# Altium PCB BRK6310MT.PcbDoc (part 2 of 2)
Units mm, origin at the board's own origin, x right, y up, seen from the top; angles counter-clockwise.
Board outline 165 x 90 mm, 4 copper layers (L1-Top, L2-Plane-1, L3-Plane-2, L4-Bottom), stack 1.539 mm thick; 47 components, 158 nets, 545 pads, 116 vias.
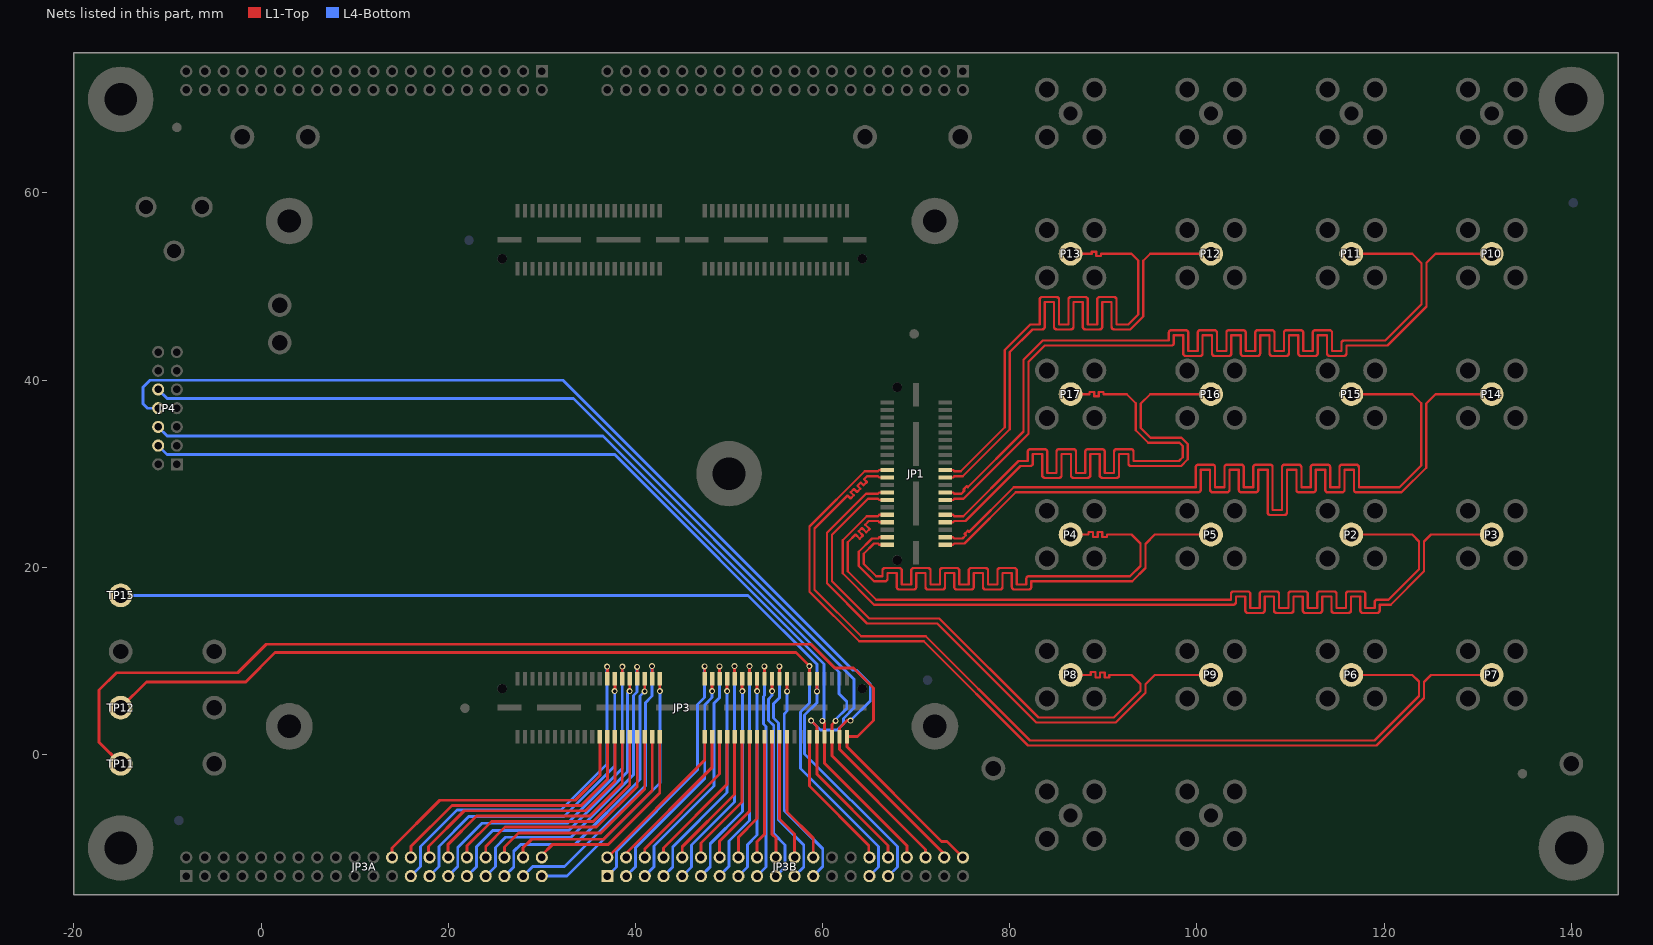
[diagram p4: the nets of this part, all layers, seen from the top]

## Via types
v1: diameter 0.635, hole 0.381, L1-Top to L4-Bottom, tented both sides, 108 vias
v2: diameter 0.889, hole 0.508, L1-Top to L4-Bottom, tented both sides, 5 vias
v3: diameter 1.27, hole 0.711, L1-Top to L4-Bottom, tented both sides, 3 vias

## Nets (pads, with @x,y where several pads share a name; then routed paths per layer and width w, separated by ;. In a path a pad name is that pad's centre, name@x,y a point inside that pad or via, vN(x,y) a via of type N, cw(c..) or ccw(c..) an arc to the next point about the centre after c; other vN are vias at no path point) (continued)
JP3_24: JP3.24 JP3A.24 | length 30.6
  L1-Top w0.305: JP3A.24@14,-11 14,-9.981 19.091,-4.891 33.569,-4.891 36.199,-2.261 JP3.24@36.199,1.914
JP3_25: JP3.25 JP3A.25 | length 38.9
  L1-Top w0.305: v1(36.972,9.384) 36.999,9.357 JP3.25@36.999,8.086
  L4-Bottom w0.305: JP3A.25@16,-13 17.033,-11.967 17.033,-9.844 20.945,-5.932 32.045,-5.932 36.972,-1.005 v1(36.972,9.384)
JP3_26: JP3.26 JP3A.26 | length 29.7
  L1-Top w0.305: JP3A.26@16,-11 16,-9.836 20.386,-5.45 34.204,-5.45 36.999,-2.654 JP3.26@36.999,1.914
JP3_27: JP3.27 JP3A.27 | length 35.3
  L1-Top w0.305: v1(37.785,6.768) 37.799,6.782 JP3.27@37.799,8.086
  L4-Bottom w0.305: JP3A.27@18,-13 19.014,-11.986 19.014,-9.818 22.189,-6.643 32.375,-6.643 37.785,-1.233 v1(37.785,6.768)
JP3_28: JP3.28 JP3A.28 | length 28.8
  L1-Top w0.305: JP3A.28@18,-11 17.897,-10.897 17.897,-9.818 21.707,-6.008 34.661,-6.008 37.799,-2.87 JP3.28@37.799,1.914
JP3_29: JP3.29 JP3A.29 | length 36.7
  L1-Top w0.305: v1(38.598,9.384) 38.599,9.383 JP3.29@38.599,8.086
  L4-Bottom w0.305: JP3A.29@20,-13 21.021,-11.979 21.021,-9.945 23.612,-7.355 32.73,-7.355 38.598,-1.487 v1(38.598,9.384)
JP3_30: JP3.30 JP3A.30 | length 27.8
  L1-Top w0.305: JP3A.30@20,-11 19.954,-10.954 19.954,-9.641 23.002,-6.593 35.118,-6.593 38.599,-3.111 JP3.30@38.599,1.914
JP3_31: JP3.31 JP3A.31 | length 33.1
  L1-Top w0.305: v1(39.385,6.768) 39.399,6.782 JP3.31@39.399,8.086
  L4-Bottom w0.305: JP3A.31@22,-13 23.002,-11.998 23.002,-9.869 24.755,-8.117 32.883,-8.117 39.157,-1.843 39.157,6.539 v1(39.385,6.768)
JP3_32: JP3.32 JP3A.32 | length 26.5
  L1-Top w0.305: JP3A.32@22,-11 22,-9.754 24.602,-7.151 35.499,-7.151 39.399,-3.251 JP3.32@39.399,1.914
JP3_33: JP3.33 JP3A.33 | length 34.4
  L1-Top w0.305: v1(40.173,9.359) 40.199,9.332 JP3.33@40.199,8.086
  L4-Bottom w0.305: JP3A.33@24,-13 25.034,-11.966 25.034,-9.945 26.126,-8.853 33.111,-8.853 39.792,-2.173 39.792,6.285 40.173,6.666 v1(40.173,9.359)
JP3_34: JP3.34 JP3A.34 | length 25.4
  L1-Top w0.305: JP3A.34@24,-11 24,-9.837 26.076,-7.761 35.855,-7.761 40.199,-3.416 JP3.34@40.199,1.914
JP3_35: JP3.35 JP3A.35 | length 30.7
  L1-Top w0.305: v1(40.985,6.742) 40.999,6.756 JP3.35@40.999,8.086
  L4-Bottom w0.305: JP3A.35@26,-13 26.99,-12.01 26.99,-10.352 27.701,-9.641 33.518,-9.641 40.477,-2.681 40.477,6.234 v1(40.985,6.742)
JP3_36: JP3.36 JP3A.36 | length 24.3
  L1-Top w0.305: JP3A.36@26,-11 26,-9.894 27.498,-8.396 36.286,-8.396 40.999,-3.683 JP3.36@40.999,1.914
JP3_37: JP3.37 JP3A.37 | length 31.5
  L1-Top w0.305: JP3.37@41.8,8.086 v1@41.8,9.408
  L4-Bottom w0.305: JP3A.37@28,-13 29.023,-11.977 32.426,-11.977 41.062,-3.341 41.062,5.523 41.773,6.234 v1(41.773,9.435)
JP3_38: JP3.38 JP3A.38 | length 23.1
  L1-Top w0.305: JP3A.38@28,-11 28,-9.977 28.92,-9.056 36.591,-9.056 41.8,-3.848 JP3.38@41.8,1.914
JP3_39: JP3.39 JP3A.39 | length 27.9
  L1-Top w0.305: JP3.39@42.6,8.086 42.6,6.779 v1(42.611,6.768)
  L4-Bottom w0.305: JP3A.39@30,-13 32.673,-13 42.611,-3.062 v1(42.611,6.768)
JP3_40: JP3.40 JP3A.40 | length 21.6
  L1-Top w0.305: JP3A.40@30,-11 30,-10.745 31.105,-9.641 37.074,-9.641 42.6,-4.115 JP3.40@42.6,1.914
JP3_41: JP3.41 JP3B.1 | length 28
  L1-Top w0.305: v1(47.386,9.409) 47.4,9.395 JP3.41@47.4,8.086
  L4-Bottom w0.305: JP3B.1@37,-13 37.963,-12.037 37.963,-10.352 46.65,-1.665 46.65,5.345 47.386,6.082 v1(47.386,9.409)
JP3_42: JP3.42 JP3B.2 | length 17.2
  L1-Top w0.305: JP3B.2@37,-11 47.4,-0.6 JP3.42@47.4,1.914
JP3_43: JP3.43 JP3B.3 | length 24.9
  L1-Top w0.305: v1(48.199,6.768) v1(48.199,6.768) JP3.43@48.2,8.086
  L4-Bottom w0.305: JP3B.3@39,-13 39.995,-12.005 39.995,-9.971 47.412,-2.554 47.412,5.295 48.199,6.082 v1(48.199,6.768)
JP3_44: JP3.44 JP3B.4 | length 16.7
  L1-Top w0.305: JP3B.4@39,-11 39,-10.575 48.2,-1.374 JP3.44@48.2,1.914
JP3_45: JP3.45 JP3B.5 | length 27
  L1-Top w0.305: v1(48.986,9.409) 49,9.395 JP3.45@49,8.086
  L4-Bottom w0.305: JP3B.5@41,-13 42.001,-11.999 42.001,-9.768 48.402,-3.367 48.402,5.472 48.986,6.057 v1(48.986,9.409)
JP3_46: JP3.46 JP3B.6 | length 16.2
  L1-Top w0.305: JP3B.6@41,-11 41,-10.099 49,-2.098 JP3.46@49,1.914
JP3_47: JP3.47 JP3B.7 | length 23.9
  L1-Top w0.305: v1(49.799,6.768) v1(49.799,6.768) JP3.47@49.801,8.086
  L4-Bottom w0.305: JP3B.7@43,-13 43.983,-12.017 43.983,-9.895 49.799,-4.078 v1(49.799,6.768)
JP3_48: JP3.48 JP3B.8 | length 15.7
  L1-Top w0.305: JP3B.8@43,-11 43,-9.988 49.801,-3.188 JP3.48@49.801,1.914
JP3_49: JP3.49 JP3B.9 | length 26.1
  L1-Top w0.305: v1(50.587,9.435) 50.601,9.421 JP3.49@50.601,8.086
  L4-Bottom w0.305: JP3B.9@45,-13 45.989,-12.011 45.989,-9.691 50.587,-5.094 v1(50.587,9.435)
JP3_50: JP3.50 JP3B.10 | length 15.2
  L1-Top w0.305: JP3B.10@45,-11 45,-9.868 50.601,-4.267 JP3.50@50.601,1.914
JP3_51: JP3.51 JP3B.11 | length 22.9
  L1-Top w0.305: JP3.51@51.401,8.086 51.401,6.792 v1(51.425,6.768)
  L4-Bottom w0.305: JP3B.11@47,-13 47.996,-12.004 47.996,-9.539 51.425,-6.11 v1(51.425,6.768)
JP3_52: JP3.52 JP3B.12 | length 14.7
  L1-Top w0.305: JP3B.12@47,-11 47,-9.468 51.401,-5.067 JP3.52@51.401,1.914
JP3_53: JP3.53 JP3B.13 | length 25.1
  L1-Top w0.305: v1(52.187,9.435) 52.201,9.421 JP3.53@52.201,8.086
  L4-Bottom w0.305: JP3B.13@49,-13 49,-12.954 50.002,-11.952 50.002,-9.234 52.187,-7.05 v1(52.187,9.435)
JP3_54: JP3.54 JP3B.14 | length 14.2
  L1-Top w0.305: JP3B.14@49,-11 49,-9.271 52.201,-6.071 JP3.54@52.201,1.914
JP3_55: JP3.55 JP3B.15 | length 21.9
  L1-Top w0.305: v1(53,6.768) v1(53,6.768) JP3.55@53.001,8.086
  L4-Bottom w0.305: JP3B.15@51,-13 51.984,-12.016 51.984,-9.641 53,-8.625 v1(53,6.768)
JP3_56: JP3.56 JP3B.16 | length 13.7
  L1-Top w0.305: JP3B.16@51,-11 51,-8.846 53.001,-6.845 JP3.56@53.001,1.914
JP3_57: JP3.57 JP3B.17 | length 24.3
  L1-Top w0.305: v1(53.787,9.409) 53.801,9.395 JP3.57@53.801,8.086
  L4-Bottom w0.305: JP3B.17@53,-13 53.965,-12.035 53.965,2.983 53.685,3.263 53.685,6.184 53.787,6.285 v1(53.787,9.409)
JP3_58: JP3.58 JP3B.18 | length 13.2
  L1-Top w0.305: JP3B.18@53,-11 53,-9.335 53.801,-8.534 JP3.58@53.801,1.914
JP3_59: JP3.59 JP3B.19 | length 22.4
  L1-Top w0.305: v1(54.6,6.768) v1(54.6,6.768) JP3.59@54.601,8.086
  L4-Bottom w0.305: v1(54.6,6.768) 54.6,6.285 54.219,5.904 54.219,3.644 54.778,3.085 54.778,-8.472 55.971,-9.666 55.971,-12.054 55.025,-13 JP3B.19@55,-13
JP3_60: JP3.60 JP3B.20 | length 13.1
  L1-Top w0.305: JP3.60@54.601,1.914 54.601,-8.524 55.006,-8.929 55.006,-10.994 JP3B.20@55,-11
JP3_61: JP3.61 JP3B.21 | length 25.7
  L1-Top w0.305: v1(55.387,9.409) 55.401,9.395 JP3.61@55.401,8.086
  L4-Bottom w0.305: v1(55.387,9.409) 55.387,6.057 54.752,5.422 54.752,3.898 55.286,3.364 55.286,-6.999 57.978,-9.691 57.978,-12.022 JP3B.21@57,-13
JP3_62: JP3.62 JP3B.22 | length 13.6
  L1-Top w0.305: JP3.62@55.401,1.914 55.401,-6.886 57,-8.485 JP3B.22@57,-11
JP3_63: JP3.63 JP3B.23 | length 23.3
  L1-Top w0.305: v1(56.2,6.742) v1(56.2,6.742) JP3.63@56.201,8.086
  L4-Bottom w0.305: v1(56.2,6.742) 56.2,4.634 55.895,4.329 55.895,-5.958 60.01,-10.072 60.01,-11.99 JP3B.23@59,-13
JP3_64: JP3.64 JP3B.24 | length 14.1
  L1-Top w0.305: JP3.64@56.201,1.914 56.201,-6.162 59,-8.961 JP3B.24@59,-11
JP3_69: JP3.69 JP3B.29 TP12.1 | length 104.7
  L1-Top w0.305: TP12.1@-15,5 -12.242,7.758 -1.636,7.758 1.488,10.883 57.14,10.883 v1(58.588,9.435) 58.602,9.421 JP3.69@58.602,8.086
  L4-Bottom w0.305: v1(58.588,9.435) 58.588,5.498 57.622,4.533 57.622,-1.487 65.979,-9.844 65.979,-12.021 JP3B.29@65,-13
JP3_70: JP3.70 JP3B.30 | length 15.6
  L1-Top w0.305: JP3.70@58.602,1.914 58.602,-3.381 64.938,-9.717 64.938,-10.938 JP3B.30@65,-11
JP3_80: JP3.80 JP3B.40 TP11.1 | length 120.9
  L1-Top w0.305: TP11.1@-15,-1 -17.308,1.308 -17.308,6.869 -15.453,8.724 -2.499,8.724 0.549,11.772 58.765,11.772 61.305,9.232 63.312,9.232 65.446,7.098 65.446,3.644 63.716,1.914 JP3.80@62.602,1.914 62.602,0.823 72.71,-9.285 73.285,-9.285 JP3B.40@75,-11
JTAG_TCK: JP3.76 JP3B.36 JP4.6 | length 108.5
  L1-Top w0.305: v1(61.382,3.593) 61.002,3.213 JP3.76@61.002,1.914 61.002,-0.142 71,-10.14 JP3B.36@71,-11
  L4-Bottom w0.305: JP4.6@-11,35 -10.022,34.022 36.54,34.022 61.763,8.8 61.763,6.488 62.575,5.676 62.575,4.914 61.382,3.72 v1(61.382,3.593)
JTAG_TDI: JP3.72 JP3B.32 JP4.10 | length 114.6
  L1-Top w0.305: v1(58.765,3.618) 59.402,2.982 JP3.72@59.402,1.914 59.402,-2.124 67,-9.722 JP3B.32@67,-11
  L4-Bottom w0.305: JP4.10@-11,39 -10.035,38.035 33.365,38.035 63.363,8.038 63.363,4.99 62.22,3.847 62.22,3.288 61.534,2.602 59.781,2.602 v1(58.765,3.618)
JTAG_TDO: JP3.78 JP3B.38 JP4.8 | length 119.8
  L1-Top w0.305: v1(62.982,3.618) 62.601,3.618 61.802,2.819 JP3.78@61.802,1.914 61.802,0.556 73,-10.642 JP3B.38@73,-11
  L4-Bottom w0.305: JP4.8@-11,37 -12.145,37 -12.151,36.994 -12.634,37.476 -12.634,39.229 -11.872,39.991 32.273,39.991 63.264,9 63.594,9 65.09,7.504 65.09,5.726 v1(62.982,3.618)
JTAG_TMS: JP3.74 JP3B.34 JP4.4 | length 105.3
  L1-Top w0.305: v1(59.985,3.593) 60.202,3.375 JP3.74@60.202,1.914 60.202,-0.943 69,-9.741 JP3B.34@69,-11
  L4-Bottom w0.305: JP4.4@-11,33 -10.041,32.041 37.785,32.041 60.162,9.663 60.162,3.771 v1(59.985,3.593)
RX101_0N: JP1.3 P5.1 | length 63.5
  L1-Top w0.241: JP1.3@66.914,23.199 66.058,23.199 65.925,23.066 65.273,23.066 63.869,21.661 63.869,20.131 65.5,18.5 66.658,18.5 ccw(c66.658,18.767) 66.925,18.767 66.925,19.384 67.928,19.384 67.928,17.883 ccw(c68.195,17.883) 68.195,17.616 69.732,17.616 ccw(c69.732,17.883) 69.999,17.883 69.999,19.384 71.002,19.384 71.002,17.883 ccw(c71.269,17.883) 71.269,17.616 72.805,17.616 ccw(c72.805,17.883) 73.072,17.883 73.072,19.384 74.075,19.384 74.075,17.883 ccw(c74.342,17.883) 74.342,17.616 75.879,17.616 ccw(c75.879,17.883) 76.145,17.883 76.145,19.384 77.149,19.384 77.149,17.883 ccw(c77.415,17.883) 77.415,17.616 78.952,17.616 ccw(c78.952,17.883) 79.219,17.883 79.219,19.384 80.222,19.384 80.222,17.883 ccw(c80.489,17.883) 80.489,17.616 82.025,17.616 ccw(c82.025,17.883) 82.292,17.883 82.292,18.5 93.078,18.5 94.5,19.922 94.5,22.5 95.5,23.5 P5.1@101.5,23.5
RX101_0P: JP1.1 P4.1 | length 63.5
  L1-Top w0.241: JP1.1@66.914,22.399 66.058,22.399 65.925,22.532 65.494,22.532 64.402,21.44 64.402,20.352 65.721,19.033 66.392,19.033 66.392,19.651 cw(c66.658,19.651) 66.658,19.917 68.195,19.917 cw(c68.195,19.651) 68.462,19.651 68.462,18.149 69.465,18.149 69.465,19.651 cw(c69.732,19.651) 69.732,19.917 71.269,19.917 cw(c71.269,19.651) 71.535,19.651 71.535,18.149 72.539,18.149 72.539,19.651 cw(c72.805,19.651) 72.805,19.917 74.342,19.917 cw(c74.342,19.651) 74.609,19.651 74.609,18.149 75.612,18.149 75.612,19.651 cw(c75.879,19.651) 75.879,19.917 77.415,19.917 cw(c77.415,19.651) 77.682,19.651 77.682,18.149 78.685,18.149 78.685,19.651 cw(c78.952,19.651) 78.952,19.917 80.489,19.917 cw(c80.489,19.651) 80.755,19.651 80.755,18.149 81.759,18.149 81.759,18.767 cw(c82.025,18.767) 82.025,19.033 92.857,19.033 93.967,20.143 93.967,22.533 93,23.5 90.382,23.5 90.382,23.233 89.887,23.233 89.887,23.767 89.391,23.767 89.391,23.233 88.896,23.233 88.896,23.767 88.401,23.767 88.401,23.5 P4.1@86.5,23.5
RX101_1N: JP1.15 P9.1 | length 63.5
  L1-Top w0.241: JP1.15@66.914,28 66.058,28 65.925,27.866 64.638,27.866 60.467,23.695 60.467,18.288 64.754,14 72.246,14 82.84,3.406 91.319,3.406 94.5,6.587 94.5,7.5 95.5,8.5 P9.1@101.5,8.5
RX101_1P: JP1.13 P8.1 | length 63.5
  L1-Top w0.241: JP1.13@66.914,27.2 66.058,27.2 65.925,27.333 64.859,27.333 61,23.474 61,18.509 64.975,14.533 72.467,14.533 83.061,3.939 91.098,3.939 93.967,6.808 93.967,7.533 93,8.5 90.636,8.5 90.636,8.233 90.141,8.233 90.141,8.767 89.645,8.767 89.645,8.233 89.15,8.233 89.15,8.8 88.655,8.8 88.655,8.5 P8.1@86.5,8.5
RX123_0N: JP1.22 P13.1 | length 63.5
  L1-Top w0.241: JP1.22@73.086,30.4 73.932,30.4 74.066,30.267 74.767,30.267 79.467,34.967 79.467,43.221 82.197,45.951 83.196,45.951 83.196,48.61 cw(c83.463,48.61) 83.463,48.876 85,48.876 cw(c85,48.61) 85.266,48.61 85.266,45.951 86.27,45.951 86.27,48.61 cw(c86.536,48.61) 86.536,48.876 88.073,48.876 cw(c88.073,48.61) 88.34,48.61 88.34,45.951 89.343,45.951 89.343,48.61 cw(c89.61,48.61) 89.61,48.876 91.146,48.876 cw(c91.146,48.61) 91.413,48.61 91.413,45.951 92.648,45.951 93.717,47.02 93.717,52.783 93,53.5 89.747,53.5 89.747,53.271 89.252,53.271 89.252,53.729 88.756,53.729 88.756,53.5 P13.1@86.5,53.5
RX123_0P: JP1.20 P12.1 | length 63.5
  L1-Top w0.241: JP1.20@73.086,29.6 73.932,29.6 74.066,29.733 74.988,29.733 80,34.746 80,43 82.418,45.418 83.463,45.418 ccw(c83.463,45.684) 83.73,45.684 83.73,48.343 84.733,48.343 84.733,45.684 ccw(c85,45.684) 85,45.418 86.536,45.418 ccw(c86.536,45.684) 86.803,45.684 86.803,48.343 87.806,48.343 87.806,45.684 ccw(c88.073,45.684) 88.073,45.418 89.61,45.418 ccw(c89.61,45.684) 89.876,45.684 89.876,48.343 90.88,48.343 90.88,45.684 ccw(c91.146,45.684) 91.146,45.418 92.869,45.418 94.25,46.799 94.25,52.75 95,53.5 P12.1@101.5,53.5
RX123_1N: JP1.10 P17.1 | length 63.5
  L1-Top w0.241: JP1.10@73.086,25.599 73.932,25.599 74.066,25.466 75.04,25.466 80.929,31.355 81.928,31.355 81.928,32.358 cw(c82.195,32.358) 82.195,32.625 83.732,32.625 cw(c83.732,32.358) 83.998,32.358 83.998,30.085 85.002,30.085 85.002,32.358 cw(c85.268,32.358) 85.268,32.625 86.805,32.625 cw(c86.805,32.358) 87.072,32.358 87.072,30.085 88.075,30.085 88.075,32.358 cw(c88.342,32.358) 88.342,32.625 89.878,32.625 cw(c89.878,32.358) 90.145,32.358 90.145,30.085 91.148,30.085 91.148,32.358 cw(c91.415,32.358) 91.415,32.625 92.952,32.625 cw(c92.952,32.358) 93.218,32.358 93.218,31.355 98.092,31.355 98.491,31.754 98.491,32.955 98.135,33.311 94.808,33.311 93.467,34.652 93.467,37.533 92.5,38.5 90.014,38.5 90.014,38.729 89.518,38.729 89.518,38.271 89.023,38.271 89.023,38.729 88.528,38.729 88.528,38.5 P17.1@86.5,38.5
RX123_1P: JP1.8 P16.1 | length 63.5
  L1-Top w0.241: JP1.8@73.086,24.799 73.932,24.799 74.066,24.933 75.261,24.933 81.15,30.822 82.195,30.822 ccw(c82.195,31.088) 82.462,31.088 82.462,32.092 83.465,32.092 83.465,29.818 ccw(c83.732,29.818) 83.732,29.552 85.268,29.552 ccw(c85.268,29.818) 85.535,29.818 85.535,32.092 86.538,32.092 86.538,29.818 ccw(c86.805,29.818) 86.805,29.552 88.342,29.552 ccw(c88.342,29.818) 88.608,29.818 88.608,32.092 89.612,32.092 89.612,29.818 ccw(c89.878,29.818) 89.878,29.552 91.415,29.552 ccw(c91.415,29.818) 91.682,29.818 91.682,32.092 92.685,32.092 92.685,31.088 ccw(c92.952,31.088) 92.952,30.822 98.313,30.822 99.024,31.533 99.024,33.176 98.356,33.844 95.029,33.844 94,34.873 94,37.5 95,38.5 P16.1@101.5,38.5
TX101_0N: JP1.9 P3.1 | length 101.6
  L1-Top w0.241: JP1.9@66.914,25.599 66.058,25.599 65.925,25.466 64.714,25.466 62.141,22.893 62.141,19.359 65.5,16 99.507,16 103.895,16 ccw(c103.895,16.267) 104.162,16.267 104.162,16.884 105.165,16.884 105.165,15.383 ccw(c105.432,15.383) 105.432,15.116 106.968,15.116 ccw(c106.968,15.383) 107.235,15.383 107.235,16.884 108.238,16.884 108.238,15.383 ccw(c108.505,15.383) 108.505,15.116 110.042,15.116 ccw(c110.042,15.383) 110.308,15.383 110.308,16.884 111.312,16.884 111.312,15.383 ccw(c111.578,15.383) 111.578,15.116 113.115,15.116 ccw(c113.115,15.383) 113.382,15.383 113.382,16.884 114.385,16.884 114.385,15.383 ccw(c114.652,15.383) 114.652,15.116 116.188,15.116 ccw(c116.188,15.383) 116.455,15.383 116.455,16.884 117.458,16.884 117.458,15.383 ccw(c117.725,15.383) 117.725,15.116 119.262,15.116 ccw(c119.262,15.383) 119.529,15.383 119.529,16 120.702,16 124.267,19.565 124.267,22.767 125,23.5 P3.1@131.5,23.5
TX101_0P: JP1.7 P2.1 | length 101.6
  L1-Top w0.241: JP1.7@66.914,24.799 66.058,24.799 65.925,24.933 64.935,24.933 64.559,24.557 65.027,24.089 64.677,23.738 64.209,24.206 63.859,23.856 64.327,23.388 63.976,23.038 63.509,23.506 62.675,22.672 62.675,19.58 65.721,16.533 99.507,16.533 103.628,16.533 103.628,17.151 cw(c103.895,17.151) 103.895,17.417 105.432,17.417 cw(c105.432,17.151) 105.698,17.151 105.698,15.649 106.702,15.649 106.702,17.151 cw(c106.968,17.151) 106.968,17.417 108.505,17.417 cw(c108.505,17.151) 108.772,17.151 108.772,15.649 109.775,15.649 109.775,17.151 cw(c110.042,17.151) 110.042,17.417 111.578,17.417 cw(c111.578,17.151) 111.845,17.151 111.845,15.649 112.848,15.649 112.848,17.151 cw(c113.115,17.151) 113.115,17.417 114.652,17.417 cw(c114.652,17.151) 114.918,17.151 114.918,15.649 115.922,15.649 115.922,17.151 cw(c116.188,17.151) 116.188,17.417 117.725,17.417 cw(c117.725,17.151) 117.992,17.151 117.992,15.649 118.995,15.649 118.995,16.267 cw(c119.262,16.267) 119.262,16.533 120.481,16.533 123.733,19.786 123.733,22.767 123,23.5 P2.1@116.5,23.5
TX101_1N: JP1.21 P7.1 | length 101.6
  L1-Top w0.241: JP1.21@66.914,30.4 66.058,30.4 65.925,30.267 64.512,30.267 58.611,24.365 58.611,17.389 63.907,12.093 70.81,12.093 81.937,0.967 119.182,0.967 124.25,6.035 124.25,7.75 125,8.5 P7.1@131.5,8.5
TX101_1P: JP1.19 P6.1 | length 101.6
  L1-Top w0.241: JP1.19@66.914,29.6 66.058,29.6 65.925,29.733 64.733,29.733 64.417,29.417 64.731,29.103 64.381,28.753 64.067,29.067 63.717,28.717 64.031,28.402 63.681,28.052 63.366,28.366 63.016,28.016 63.33,27.702 62.98,27.352 62.666,27.666 59.144,24.144 59.144,17.61 64.128,12.626 71.031,12.626 82.158,1.5 118.961,1.5 123.717,6.256 123.717,7.783 123,8.5 P6.1@116.5,8.5
TX123_0N: JP1.16 P11.1 | length 101.6
  L1-Top w0.241: JP1.16@73.086,28 73.932,28 74.066,27.866 74.841,27.866 75.171,28.196 75.045,28.322 75.396,28.672 75.521,28.546 81.471,34.496 81.471,42.184 83.51,44.224 96.999,44.224 96.999,45.062 cw(c97.265,45.062) 97.265,45.329 98.802,45.329 cw(c98.802,45.062) 99.069,45.062 99.069,43.119 100.072,43.119 100.072,45.062 cw(c100.339,45.062) 100.339,45.329 101.876,45.329 cw(c101.876,45.062) 102.142,45.062 102.142,43.119 103.146,43.119 103.146,45.062 cw(c103.412,45.062) 103.412,45.329 104.949,45.329 cw(c104.949,45.062) 105.216,45.062 105.216,43.119 106.219,43.119 106.219,45.062 cw(c106.486,45.062) 106.486,45.329 108.022,45.329 cw(c108.022,45.062) 108.289,45.062 108.289,43.119 109.292,43.119 109.292,45.062 cw(c109.559,45.062) 109.559,45.329 111.096,45.329 cw(c111.096,45.062) 111.362,45.062 111.362,43.119 112.366,43.119 112.366,45.062 cw(c112.632,45.062) 112.632,45.329 114.169,45.329 cw(c114.169,45.062) 114.436,45.062 114.436,43.119 115.439,43.119 115.439,43.957 cw(c115.706,43.957) 115.706,44.224 120.13,44.224 124,48.093 124,52.5 123,53.5 P11.1@116.5,53.5
TX123_0P: JP1.14 P10.1 | length 101.6
  L1-Top w0.241: JP1.14@73.086,27.2 73.932,27.2 74.066,27.333 75.062,27.333 82.004,34.275 82.004,41.963 83.731,43.69 97.265,43.69 ccw(c97.265,43.957) 97.532,43.957 97.532,44.795 98.535,44.795 98.535,42.852 ccw(c98.802,42.852) 98.802,42.586 100.339,42.586 ccw(c100.339,42.852) 100.606,42.852 100.606,44.795 101.609,44.795 101.609,42.852 ccw(c101.876,42.852) 101.876,42.586 103.412,42.586 ccw(c103.412,42.852) 103.679,42.852 103.679,44.795 104.682,44.795 104.682,42.852 ccw(c104.949,42.852) 104.949,42.586 106.486,42.586 ccw(c106.486,42.852) 106.752,42.852 106.752,44.795 107.756,44.795 107.756,42.852 ccw(c108.022,42.852) 108.022,42.586 109.559,42.586 ccw(c109.559,42.852) 109.826,42.852 109.826,44.795 110.829,44.795 110.829,42.852 ccw(c111.096,42.852) 111.096,42.586 112.632,42.586 ccw(c112.632,42.852) 112.899,42.852 112.899,44.795 113.902,44.795 113.902,42.852 ccw(c114.169,42.852) 114.169,42.586 115.706,42.586 ccw(c115.706,42.852) 115.973,42.852 115.973,43.69 120.351,43.69 124.533,47.872 124.533,52.533 125.5,53.5 P10.1@131.5,53.5
TX123_1N: JP1.4 P15.1 | length 101.6
  L1-Top w0.241: JP1.4@73.086,23.199 73.932,23.199 74.066,23.066 74.951,23.066 75.298,23.413 75.154,23.557 75.505,23.907 75.648,23.763 80.43,28.545 99.869,28.545 99.869,30.697 cw(c100.136,30.697) 100.136,30.963 101.672,30.963 cw(c101.672,30.697) 101.939,30.697 101.939,28.545 102.942,28.545 102.942,30.697 cw(c103.209,30.697) 103.209,30.963 104.746,30.963 cw(c104.746,30.697) 105.012,30.697 105.012,28.545 106.016,28.545 106.016,30.697 cw(c106.282,30.697) 106.282,30.963 107.819,30.963 cw(c107.819,30.697) 108.086,30.697 108.086,26.126 109.089,26.126 109.089,30.697 cw(c109.356,30.697) 109.356,30.963 110.893,30.963 cw(c110.893,30.697) 111.159,30.697 111.159,28.545 112.163,28.545 112.163,30.697 cw(c112.429,30.697) 112.429,30.963 113.966,30.963 cw(c113.966,30.697) 114.233,30.697 114.233,28.545 115.236,28.545 115.236,30.697 cw(c115.503,30.697) 115.503,30.963 117.039,30.963 cw(c117.039,30.697) 117.306,30.697 117.306,28.545 121.647,28.545 123.967,30.864 123.967,37.533 123,38.5 P15.1@116.5,38.5
TX123_1P: JP1.2 P14.1 | length 101.6
  L1-Top w0.241: JP1.2@73.086,22.399 73.932,22.399 74.066,22.532 75.172,22.532 80.651,28.011 100.136,28.011 ccw(c100.136,28.278) 100.402,28.278 100.402,30.43 101.406,30.43 101.406,28.278 ccw(c101.672,28.278) 101.672,28.011 103.209,28.011 ccw(c103.209,28.278) 103.476,28.278 103.476,30.43 104.479,30.43 104.479,28.278 ccw(c104.746,28.278) 104.746,28.011 106.282,28.011 ccw(c106.282,28.278) 106.549,28.278 106.549,30.43 107.552,30.43 107.552,25.86 ccw(c107.819,25.86) 107.819,25.593 109.356,25.593 ccw(c109.356,25.86) 109.623,25.86 109.623,30.43 110.626,30.43 110.626,28.278 ccw(c110.893,28.278) 110.893,28.011 112.429,28.011 ccw(c112.429,28.278) 112.696,28.278 112.696,30.43 113.699,30.43 113.699,28.278 ccw(c113.966,28.278) 113.966,28.011 115.503,28.011 ccw(c115.503,28.278) 115.769,28.278 115.769,30.43 116.773,30.43 116.773,28.278 ccw(c117.039,28.278) 117.039,28.011 121.868,28.011 124.5,30.643 124.5,37.5 125.5,38.5 P14.1@131.5,38.5
VREF_BANK1: JP3.71 JP3B.31 TP15.1 | length 106.5
  L1-Top w0.305: v1(59.4,6.742) v1(59.4,6.742) JP3.71@59.402,8.086
  L4-Bottom w0.305: TP15.1@-15,17 52.038,17 59.4,9.638 v1(59.4,6.742) 59.4,5.523 58.08,4.202 58.08,0.062 67.986,-9.844 67.986,-12.014 JP3B.31@67,-13
pads on no net: JP1.25 JP1.27 JP1.31 JP1.33 JP1.MH JP2.MH JP3.MH JP4.12 JP4.14 P1.3

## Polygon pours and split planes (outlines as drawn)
DGND on L2-Plane-1 (split plane): 144.49,-14.49 -19.49,-14.49 -19.49,74.49 144.49,74.49
+VDC on L3-Plane-2 (split plane): 78.744,60.891 54.973,37.12 54.949,37.123 11.069,37.123 1.67,46.522 -8.236,56.428 -9.812,58.004 -9.812,60.84 -2.876,67.776 -0.142,67.776 18.63,49.005 18.683,48.964 18.745,48.938 18.811,48.93 57.953,48.93 58.019,48.938 58.081,48.964 58.134,49.005 60.166,51.037 60.206,51.09 60.219,51.121 60.232,51.151 60.241,51.218 60.241,59.062 69.234,68.055 69.274,68.108 69.3,68.169 69.309,68.236 69.309,74.49 78.744,74.49
DGND on L3-Plane-2 (split plane): 144.49,-14.49 80.256,-14.49 80.256,-13 80.247,-12.934 80.222,-12.872 80.181,-12.819 67.48,-0.117 67.48,4.507 67.48,6.692 67.471,6.758 67.445,6.82 67.405,6.873 64.687,9.591 64.634,9.631 64.572,9.657 64.506,9.666 63.037,9.666 55.256,17.447 55.256,36.678 79.181,60.603 79.222,60.656 79.24,60.7 79.247,60.718 79.256,60.784 79.256,74.49 144.49,74.49
+3.3VDD on L3-Plane-2 (split plane): 68.796,68.342 59.803,59.349 59.763,59.296 59.737,59.234 59.728,59.168 59.728,51.324 57.846,49.442 18.917,49.442 0.146,68.214 0.092,68.254 0.031,68.28 -0.036,68.289 -2.982,68.289 -3.048,68.28 -3.092,68.262 -3.11,68.254 -3.163,68.214 -10.25,61.127 -10.29,61.074 -10.316,61.012 -10.325,60.946 -10.325,57.898 -10.316,57.832 -10.29,57.77 -10.25,57.717 -8.599,56.066 -8.523,55.99 1.307,46.16 10.781,36.686 10.835,36.645 10.896,36.619 10.963,36.611 54.744,36.611 54.744,17.34 54.753,17.274 54.778,17.212 54.819,17.159 62.75,9.228 62.803,9.188 62.847,9.169 62.865,9.162 62.931,9.153 64.4,9.153 66.967,6.585 66.967,4.507 66.967,-0.224 66.976,-0.29 67.002,-0.352 67.042,-0.405 79.744,-13.106 79.744,-14.49 -19.49,-14.49 -19.49,74.49 68.796,74.49

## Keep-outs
Keep-Out Layer:
  the board outline again, w0.178

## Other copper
L3-Plane-2 (plane layer: these items are gaps in the copper):
  lines w0.508: -8.418,56.247 1.488,46.341 10.963,36.867 54.949,36.867 55,36.816 55,17.34 62.931,9.409 64.506,9.409 67.224,6.692 67.224,4.507 67.224,-0.224 80,-13 80,-15 ; -8.341,56.171 -10.069,57.898 -10.069,60.946 -2.982,68.033 -0.036,68.033 18.811,49.186 57.953,49.186 59.985,51.218 59.985,59.168 69.052,68.236 69.052,75.068 ; 55.003,36.788 79,60.784 79,75 ; 76.469,74.967 76.495,74.941

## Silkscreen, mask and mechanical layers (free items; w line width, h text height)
Top Overlay:
  lines w0.203: 0,15 0,0 15,0 ; 0,45 0,60 15,60 ; 60,0 75,0 75,15 ; 60,60 75,60 75,45
  lines w0.508: 87.5,-12.5 81,-12.5 81,-1 107,-1 107,-12 ; 87.5,2.5 81,2.5 81,14 107,14 107,3 ; 87.5,17.5 81,17.5 81,29 107,29 107,18 ; 87.5,32.5 81,32.5 81,44 107,44 107,33 ; 87.5,47.5 81,47.5 81,59 107,59 107,48 ; 87.5,62.5 81,62.5 81,74 107,74 107,63 107,62.5 101.5,62.5 ; 101.5,-12.5 107,-12.5 ; 101.5,2.5 107,2.5 ; 101.5,17.5 107,17.5 ; 101.5,32.5 107,32.5 ; 101.5,47.5 107,47.5 ; 117.5,2.5 111,2.5 111,14 137,14 137,3 ; 117.5,17.5 111,17.5 111,29 137,29 137,18 ; 117.5,32.5 111,32.5 111,44 137,44 137,33 ; 117.5,47.5 111,47.5 111,59 137,59 137,48 ; 117.5,62.5 111,62.5 111,74 137,74 137,63 ; 131.5,2.5 137,2.5 ; 131.5,17.5 137,17.5 ; 131.5,32.5 137,32.5 ; 131.5,47.5 137,47.5 ; 131.5,62.5 137,62.5
  text "-" at 91.75,64 h1.27
  text "+" at 95.25,64 h1.27
  text "-" at 121.75,64 h1.27
  text "+" at 125.25,64 h1.27
  text "-" at 91.75,49 h1.27
  text "+" at 95.25,49 h1.27
  text "-" at 121.75,49 h1.27
  text "+" at 125.25,49 h1.27
  text "XILINX JTAG" at -5,44 h1.27 r270
  text "TDI" at -16.7,38.6 h1.02
  text "TDO" at -17,36.6 h1.02
  text "TCK" at -17,34.6 h1.02
  text "-" at 91.75,34 h1.27
  text "+" at 95.25,34 h1.27
  text "-" at 121.75,34 h1.27
  text "+" at 125.25,34 h1.27
  text "TMS" at -17,32.6 h1.02
  text "+1.8V" at -18.8,30.6 h1.02
  text "+" at 91.75,19 h1.27
  text "-" at 95.25,19 h1.27
  text "+" at 121.75,19 h1.27
  text "-" at 125.25,19 h1.27
  text "+" at 91.75,4 h1.27
  text "-" at 95.25,4 h1.27
  text "+" at 121.75,4 h1.27
  text "-" at 125.25,4 h1.27
  text "BRK6310MT" at 121.386,-8.623 h1.02
  text "20130411" at 121.386,-10.623 h1.02
  text "+" at 91.75,-11 h1.27
  text "-" at 95.25,-11 h1.27
Mechanical 2:
  the board outline again, w0.203
Drill Drawing:
  lines w0.203: 70.524,-41.148 185.476,-41.148 ; 70.524,-37.196 185.476,-37.196 ; 69,-79.73 ccw(c70.27,-79.73) 70.27,-81 185.73,-81 ccw(c185.73,-79.73) 187,-79.73 187,-29.27 ccw(c185.73,-29.27) 185.73,-28 70.27,-28 ccw(c70.27,-29.27) 69,-29.27 69,-79.73
  text ":::" at 97.5,77.5 h1.27 r180
  text ":::" at 34.541,77.247 h1.27 r180
  text ":::" at -21,47 h1.27 r90
  text ":::" at 147,47 h1.27 r90
  text ":::" at 147,16 h1.27 r90
  text ":::" at -21.5,13.5 h1.27 r90
  text ".LEGEND" at 150,-14 h1.27
  text ":::" at 97.541,-15.753 h1.27 r180
  text ":::" at 34.041,-16.253 h1.27 r180
  text "NOTES" at -19.371,-27.71 h1.27
  text "1. MATERIAL SELECTION:" at -19.371,-30.25 h1.27
  text "4-LAYER, 370HR, 0.062\" +/- 0.005 THICK" at -16.196,-32.155 h1.27
  text "SURFACE FINISH: ENIG (ELECTROLESS NICKEL, IMMERSION GOLD)" at -16.196,-34.06 h1.27
  text "Layer Stack Up Detail for: BRK6310MT.PcbDoc" at 70.524,-34.589 h2.62
  text "2. SOLDER RESIST: GREEN LPI" at -19.371,-37.235 h1.27
  text "Layer" at 70.524,-38.669 h0.91
  text "Gerber" at 95.162,-38.669 h0.91
  text "Copper" at 107.622,-38.669 h0.91
  text "Dielectric" at 121.576,-38.669 h0.91
  text "Dielectric" at 136.169,-38.669 h0.91
  text "Dielectric" at 154.459,-38.669 h0.91
  text "Dielectric" at 169.052,-38.669 h0.91
  text "3. SILKSCREEN: WHITE / DO NOT REMOVE OVER TENTED VIAS." at -19.371,-40.41 h1.27
  text "Name" at 70.524,-40.498 h0.91
  text "Document" at 95.162,-40.498 h0.91
  text "Thickness" at 107.622,-40.498 h0.91
  text "Height" at 121.576,-40.498 h0.91
  text "Material" at 136.169,-40.498 h0.91
  text "Constant" at 154.459,-40.498 h0.91
  text "Type" at 169.052,-40.498 h0.91
  text "4. LOT CODE IDENTIFICATION: ADD TO SILKSCREEN" at -19.371,-43.585 h1.27
  text "Top Solder Mask" at 70.524,-44.139 h1.27
  text "(.GTS)" at 95.162,-44.139 h1.27
  text "0.4mil" at 121.576,-44.139 h1.27
  text "Solder Resist" at 136.169,-44.139 h1.27
  text "3.50" at 154.459,-44.139 h1.27
  text "5. DRILL SIZES ARE FINISHED SIZE AFTER PLATING." at -19.371,-46.76 h1.27
  text "L1-Top" at 70.524,-49.917 h1.27
  text "(.GTL)" at 95.162,-49.917 h1.27
  text "2.1mil" at 107.622,-49.917 h1.27
  text "6. ELECTRICAL BARE BOARD TEST REQUIRED" at -19.371,-49.935 h1.27
  text "7.3mil" at 121.576,-52.807 h1.27
  text "FR-4" at 136.169,-52.807 h1.27
  text "4.80" at 154.459,-52.807 h1.27
  text "PrePreg" at 169.052,-52.807 h1.27
  text "7. FABRICATE TO MEET EU ROHS DIRECTIVE" at -19.371,-53.11 h1.27
  text "L2-Plane-1" at 70.524,-55.696 h1.27
  text "(.GP1)" at 95.162,-55.696 h1.27
  text "1.4mil" at 107.622,-55.696 h1.27
  text "8. BOARD TO BE IMPEDANCE CONTROLLED:" at -19.427,-56.203 h1.27
  text "39mil" at 121.576,-58.585 h1.27
  text "FR-4" at 136.169,-58.585 h1.27
  text "4.80" at 154.459,-58.585 h1.27
  text "Core" at 169.052,-58.585 h1.27
  text "50-OHM IMPEDANCE ON 12.00mil TRACES (MICROSTRIP)" at -15.911,-58.815 h1.27
  text "100-OHM DIFFERENTIAL ON 9.50mil TRACES (MICROSTRIP)" at -15.987,-61.076 h1.27
  text "L3-Plane-2" at 70.524,-61.474 h1.27
  text "(.GP2)" at 95.162,-61.474 h1.27
  text "1.4mil" at 107.622,-61.474 h1.27
  text "9. PANELIZATION:" at -19.371,-64.169 h1.27
  text "7.3mil" at 121.576,-64.363 h1.27
  text "FR-4" at 136.169,-64.363 h1.27
  text "4.80" at 154.459,-64.363 h1.27
  text "PrePreg" at 169.052,-64.363 h1.27
  text "2-PIECES PER PANEL" at -16.196,-66.074 h1.27
  text "L4-Bottom" at 70.524,-67.252 h1.27
  text "(.GBL)" at 95.162,-67.252 h1.27
  text "2.1mil" at 107.622,-67.252 h1.27
  text "GM1 CONTAINS BOARD DIMENSIONS" at -16.196,-68.074 h1.27
  text "GM2 CONTAINS BOARD OUTLINE" at -16.196,-70.074 h1.27
  text "0.25-IN RAILS ON ALL SIDES" at -16.196,-71.979 h1.27
  text "Bottom Solder Mask" at 70.524,-73.031 h1.27
  text "(.GBS)" at 95.162,-73.031 h1.27
  text "0.4mil" at 121.576,-73.031 h1.27
  text "Solder Resist" at 136.169,-73.031 h1.27
  text "3.50" at 154.459,-73.031 h1.27
  text "0.25-IN TAB ROUTING WITH MOUSE-BITES FOR BOARD SEPARATION" at -16.196,-73.884 h1.27
  text "MOUSE BITE LOCATIONS INDICATED BY :::" at -16.114,-76.011 h1.27

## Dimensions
-20,-15 to 145,-15 on Mechanical 1
-15,-10 to 140,-10 on Mechanical 1
-15,-10 to -15,70 on Mechanical 1
-20,75 to -20,-15 on Mechanical 1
